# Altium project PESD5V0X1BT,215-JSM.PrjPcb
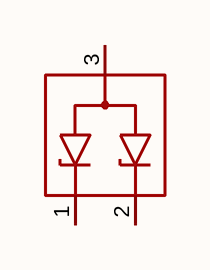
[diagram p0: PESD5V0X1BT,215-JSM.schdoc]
1 sheet, 1 parts. Net scope: global (net labels, ports and power ports of the same name join across sheets).

## Sheet PESD5V0X1BT,215-JSM.schdoc
size 127 x 101 mm

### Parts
D?  pesd5v0x1bt,215-jsm  [SOT-23-3_L2.9-W1.3-P1.90-LS2.4-BR]  (value not drawn)

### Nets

Not connected (* = marked no-connect by the designer): D? 1(C1) 2(C2) 3(A)

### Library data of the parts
D? = pesd5v0x1bt,215-jsm: 极性:-;反向截止电压(Vrwm):5V;钳位电压:15V;峰值脉冲电流(Ipp):3.5A@8/20us;峰值脉冲功率(Ppp):45W@8/20us;击穿电压(VBR):7V;; Manufacturer: JSMSEMI(杰盛微); AddInBom: yes; ModelId: c62791f0466c4ae2a892c056b845b0ca; ModelName: SOT-23-3P_L2.9-W1.3-H1.0-LS2.4-P0.95; ModelTransform: 98.425,114.173,0,180,0,0,0.0005,-0.0005,0; Reverse Stand-Off Voltage (Vrwm): 5V; Clamping Voltage: 15V; Voltage - Breakdown: 7V; Reverse Leakage Current (Ir): 500nA; Number of Channels: 双路; level of protection: IEC 61000-4-4；IEC 61000-4-5；IEC 61000-4-2; Type: ESD; Junction Capacitance: 0.7pF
